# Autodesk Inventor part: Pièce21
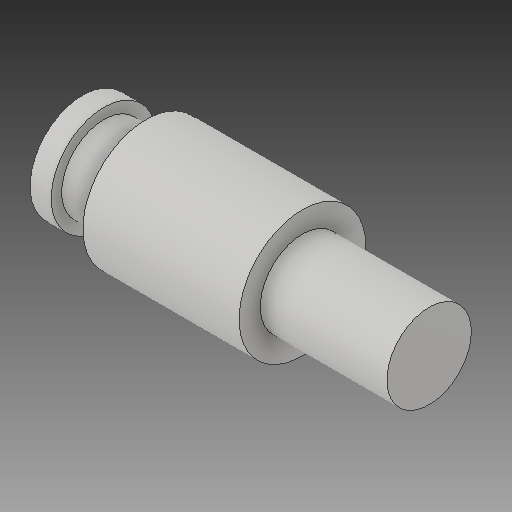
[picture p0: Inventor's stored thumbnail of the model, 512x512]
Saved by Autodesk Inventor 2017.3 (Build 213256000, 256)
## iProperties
Created: 2007-12
Part Number: Pièce21
Material: Générique
Document SubType Name: Modeling
Designer: ficho
Density: 1 g/cm^3
Appearance: Par défaut
Author: ficho
Sending System: SolidWorks 2009
Last Author: christophe
Last Saved: 2011-02-10
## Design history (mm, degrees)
feature "Révolution1"
node "Solide1"
